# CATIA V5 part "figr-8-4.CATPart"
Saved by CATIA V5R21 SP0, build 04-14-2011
Part number: Part1
Bounding box of the stored display mesh (mm): x 4.549 to 89.781, y -52.238 to 26.36, z 54 to 147.773
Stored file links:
  D:\CATIA V5R21 E-RESOURCES\CATIA-V5R21\catia-v5r21-prt\c08-catia-v5r20-prt\c08-catia-v5r21-figr-8-4.CATPart
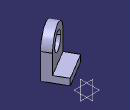
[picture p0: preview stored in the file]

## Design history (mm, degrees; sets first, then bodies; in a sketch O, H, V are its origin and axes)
Body1 (main body)
  Sketch1 on yz-plane, origin (0, 0, 0), H (0, 1, 0), V (0, 0, 1)
    point P1 (-104.4861, 0)
    line L1 (-104.4861, 0) -> (-104.4861, 44.267)
    arc A1 centre (-69.7903, 44.267) radius 34.6958 from (-104.4861, 44.267) to (-35.0946, 44.267) cw
    line L2 (-35.0946, 44.267) -> (-35.0946, 0)
    point P5 (-35.0946, 0)
    line L3 (-35.0946, 0) -> (-104.4861, 0)
    circle A2 centre (-69.7903, 44.267) radius 19.5413
    coincidence: P1 H, P5 H
    vertical: L1 V
    tangency: A1 L1, L2 A1
    horizontal: L3 H
  Pad1: profile Sketch1, direction (1, 0, 0), length 20
  Sketch2 on face of Pad1, origin (0, 0, 0), H (0, -1, 0), V (0, 0, 1)
    point P1 (35.0946, 0)
    line L1 (35.0946, 0) -> (104.4861, 0)
    line L2 (104.4861, 0) -> (104.4861, -15)
    line L3 (104.4861, -15) -> (35.0946, -15)
    line L4 (35.0946, -15) -> (35.0946, 0)
    reference projected line E1 (35.0946, 0) -> (35.0946, 44.267) from edge [face of Pad1 | face of Pad1]
    reference projected line E2 (104.4861, 44.267) -> (104.4861, 0) from edge [face of Pad1 | face of Pad1]
    distance L3 L1 = 15
    coincidence: P1 H, L4 E1, L2 E2
    horizontal: L1 H, L3 H
    vertical: L2 V, L4 V
  Pad2: profile Sketch2, direction (1, 0, 0), length 50
  Translate1: ToTransfor Pad2, Direction xy-plane, Length 69
  Rotate1: ToTransfor Translate1, Axis edge, Angle 121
